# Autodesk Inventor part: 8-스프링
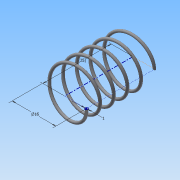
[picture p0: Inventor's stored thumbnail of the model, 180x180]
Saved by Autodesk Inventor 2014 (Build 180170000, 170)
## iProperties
Created: 2015-06
Part Number: 8-스프링
Material: 강철, 연강
Document SubType Name: Modeling
Designer: Administrator
Density: 7.86 g/cm^3
Appearance: 강철
Mass: 1.53535 g
Surface Area: 7.89038 cm^2
Volume: 0.195337 cm^3
Author: Administrator
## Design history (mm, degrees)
sketch "스케치1"
  geometry: L1 (0, 0)-(8, 0); L2 (8, 0)-(8, 21.5); L3 (8, 21.5)-(0, 21.5); L4 (0, 21.5)-(0, 0); C1 r 0.5 at (8, 0)
  constraints: 8 end point, 2 parallel, 1 centre point, 1 coincident, 1 horizontal, 1 perpendicular
  dimensions: "d0" = 21.5 distance of L3.end L1.start (derived); "d1" = 16 diameter of L1.end L4; "d2" = 1 diameter of C1
feature "코일1" sketch "스케치1" pitch "d3" = 10; turns "d5" = 5; dims "d4" = 21.5 (= d0), "d6" = 0, angle "d7" = 90 deg, angle "d8" = 90 deg, "d9" = 0, "d10" = 0
sketch "스케치2"
  geometry: L1 (15.5, -10)-(-15.5, -10); L2 (-15.5, -10)-(-15.5, 0); L3 (-15.5, 0)-(15.5, 0); L4 (15.5, 0)-(15.5, -10); L5 (-20, 31.5)-(20, 31.5); L6 (20, 31.5)-(20, 21.5); L7 (20, 21.5)-(-20, 21.5); L8 (-20, 21.5)-(-20, 31.5); 3 further points
  constraints: 16 end point, 4 parallel, 2 horizontal, 2 midpoint, 2 perpendicular, 1 coincident, 1 vertical alignment
  dimensions: "d11" = 10 distance of L3.end L1.start; "d12" = 31 distance of L1.start L1.end; "d13" = 21.5 distance between parallel lines of L3 L7 (= d0); "d14" = 10 distance of L5.end L6.end; "d15" = 40 distance of L5.start L5.end
extrude "돌출1" cut sketch "스케치2" stored distance "d16" = 0; taper "d17" = 0 deg
node "솔리드1"
